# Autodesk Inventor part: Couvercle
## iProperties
Author: patrick
Shininess: 20.0
Angle Display Precision: 2
Document Length Units: 11269
Document Angle Units: 11283
Document Time Units: 11279
Document Mass Units: 11290
Document Length Units Precision: 3
Document Angle Units Precision: 2
Compacted: True
PropertySet Name: _Private Model Information
Created: 2002-10
Part Number: Couvercle
Material: Par défaut
Document SubType Name: Modélisation
Designer: patrick
Control State: 0
Master: False
Checked Out: False
PropertySet Name: Design Tracking Control
Density: 0.0
Volumn: 0.0
Area: 0.0
PropertySet Name: Model Information
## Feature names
1. Extrusion1
2. Congé1 [Fillet]
3. Coque1
4. Extrusion2
5. Extrusion3
6. Extrusion4
7. Extrusion5
8. Extrusion7
